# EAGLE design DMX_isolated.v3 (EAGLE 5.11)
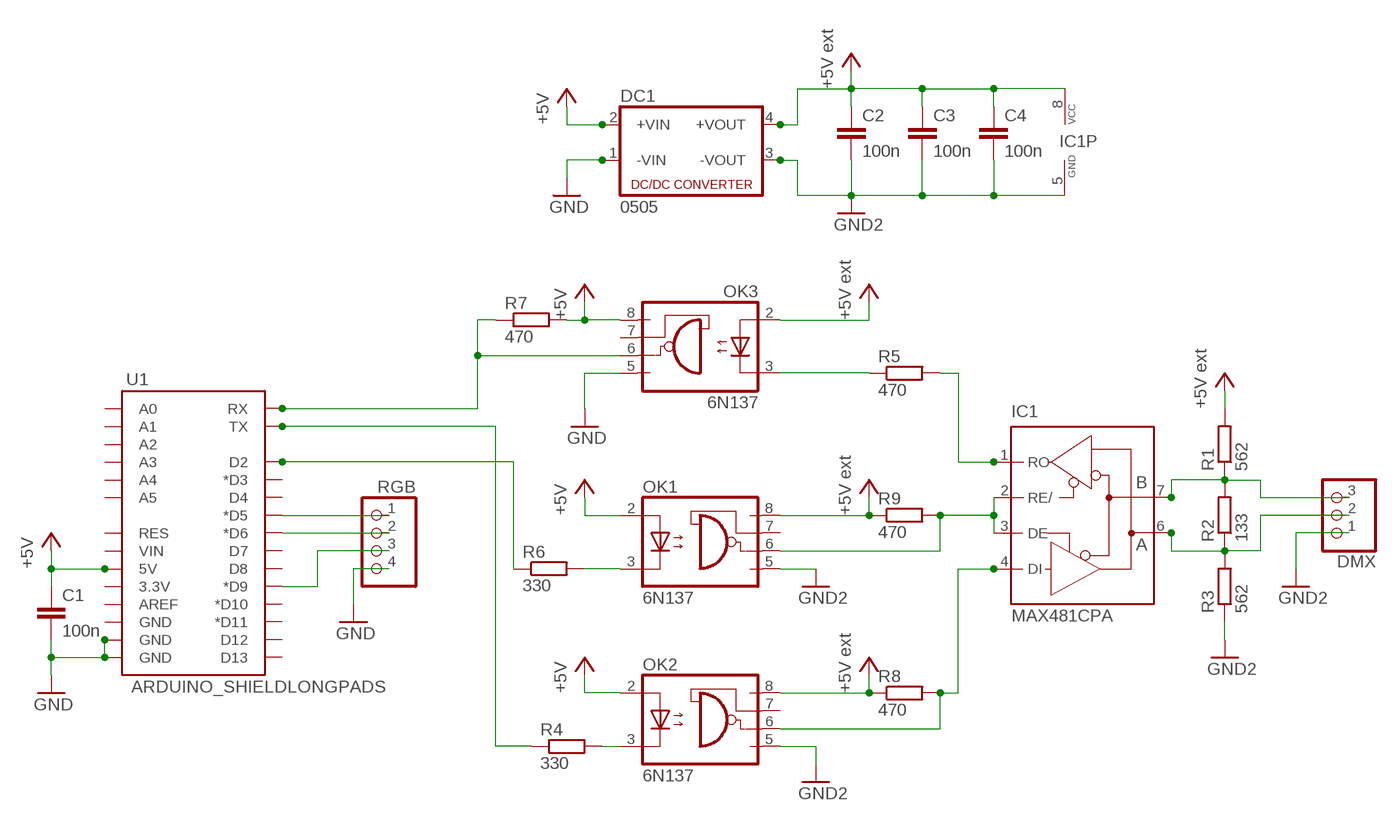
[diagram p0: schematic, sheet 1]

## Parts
C1  100n  C5/3  [C5B3]
C2  100n  C7.5/3  [C7.5B3]
C3  100n  C7.5/3  [C7.5B3]
C4  100n  C7.5/3  [C7.5B3]
DC1  0505  NME  [NME]
DMX  PINHD-1X3  [1X03]
IC1  MAX481CPA  [DIL08]
OK1  6N137  [DIL08]
OK2  6N137  [DIL08]
OK3  6N137  [DIL08]
R1  562  R-EU_0207/10  [0207/10]
R2  133  R-EU_0207/10  [0207/10]
R3  562  R-EU_0207/10  [0207/10]
R4  330  R-EU_0207/10  [0207/10]
R5  470  R-EU_0207/10  [0207/10]
R6  330  R-EU_0207/10  [0207/10]
R7  470  R-EU_0207/10  [0207/10]
R8  470  R-EU_0207/10  [0207/10]
R9  470  R-EU_0207/10  [0207/10]
RGB  PINHD-1X4  [1X04]
U1  ARDUINO_SHIELDLONGPADS  [DUEMILANOVE_SHIELD_LONGPADS]

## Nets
+5V: C1.1 DC1.2(+VIN) OK1.2(A) OK2.2(A) OK3.8(VCC) R7.2 U1.5V
+5V_EXT: C2.1 C3.1 C4.1 DC1.4(+VOUT) IC1.8(VCC) OK1.8(VCC) OK2.8(VCC) OK3.2(A) R1.2 R8.1 R9.1 ; supply symbol labelled +5V ext
D2: R4.1 U1.TX
GND: C1.2 DC1.1(-VIN) OK3.5(GND) RGB.4 U1.GND@0(GND) U1.GND@1(GND)
GND_EXT: C2.2 C3.2 C4.2 DC1.3(-VOUT) DMX.1 IC1.5(GND) OK1.5(GND) OK2.5(GND) R3.1 ; supply symbol labelled GND2
N$1: R6.1 U1.D2
N$2: RGB.1 U1.D5(*D5)
N$3: OK1.3(C) R6.2
N$4: RGB.2 U1.D6(*D6)
N$5: OK2.3(C) R4.2
N$6: IC1.2(RE/) IC1.3(DE) OK1.6(VO) R9.2
N$7: IC1.4(DI) OK2.6(VO) R8.2
N$8: OK3.3(C) R5.1
N$9: IC1.1(RO) R5.2
N$10: OK3.6(VO) R7.1 U1.RX
N$11: RGB.3 U1.D9(*D9)
N$15: DMX.3 IC1.7(B) R1.1 R2.2
N$17: DMX.2 IC1.6(A) R2.1 R3.2
Unconnected: OK1.7(VE) OK2.7(VE) OK3.7(VE) U1.3.3V U1.A0 U1.A1 U1.A2 U1.A3 U1.A4 U1.A5 U1.AREF U1.D3(*D3) U1.D4 U1.D7 U1.D8 U1.D10(*D10) U1.D11(*D11) U1.D12 U1.D13 U1.GND@2(GND) U1.RES U1.VIN

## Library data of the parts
C1-C4 = capacitor-wima:C: CAPACITOR
DC1 = dc-dc-converter:NME: DC-DC CONVERTER; MF: C & D TECHNOLOGIES, INC; MPN: NME1205D; OC_FARNELL: 1021466; OC_NEWARK: 98B8198
DMX = pinhead:PINHD-1X3: PIN HEADER
IC1 = maxim:MAX481CPA: RS485 TRANSEIVER; MPN: MAX481CPA+; OC_FARNELL: unknown; OC_NEWARK: 99K3445
OK1-OK3 = optocoupler:6N137: MOTOROLA OPTO COUPLER; MPN: 6N137; OC_FARNELL: 1328376; OC_NEWARK: 52M1895
R1-R9 = resistor:R-EU_: RESISTOR, European symbol
RGB = pinhead:PINHD-1X4: PIN HEADER
U1 = SparkFun:ARDUINO_SHIELD

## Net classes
1 power: width 0.508 mm

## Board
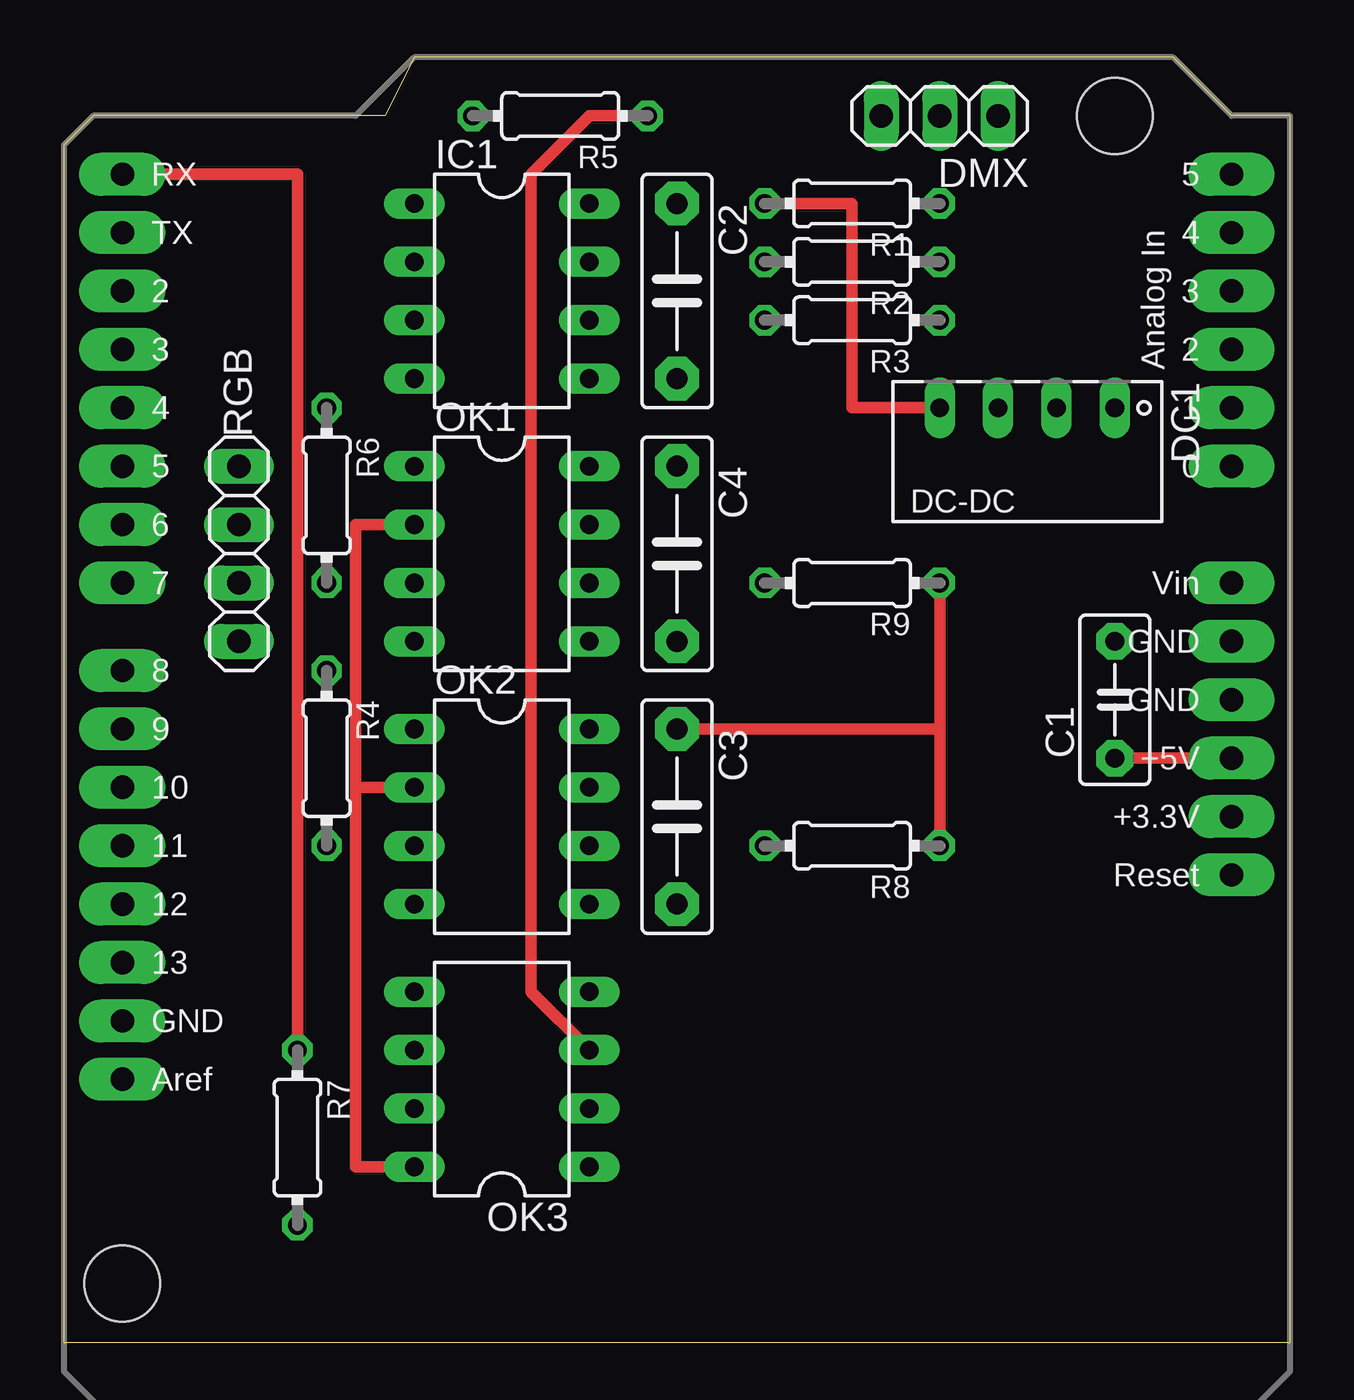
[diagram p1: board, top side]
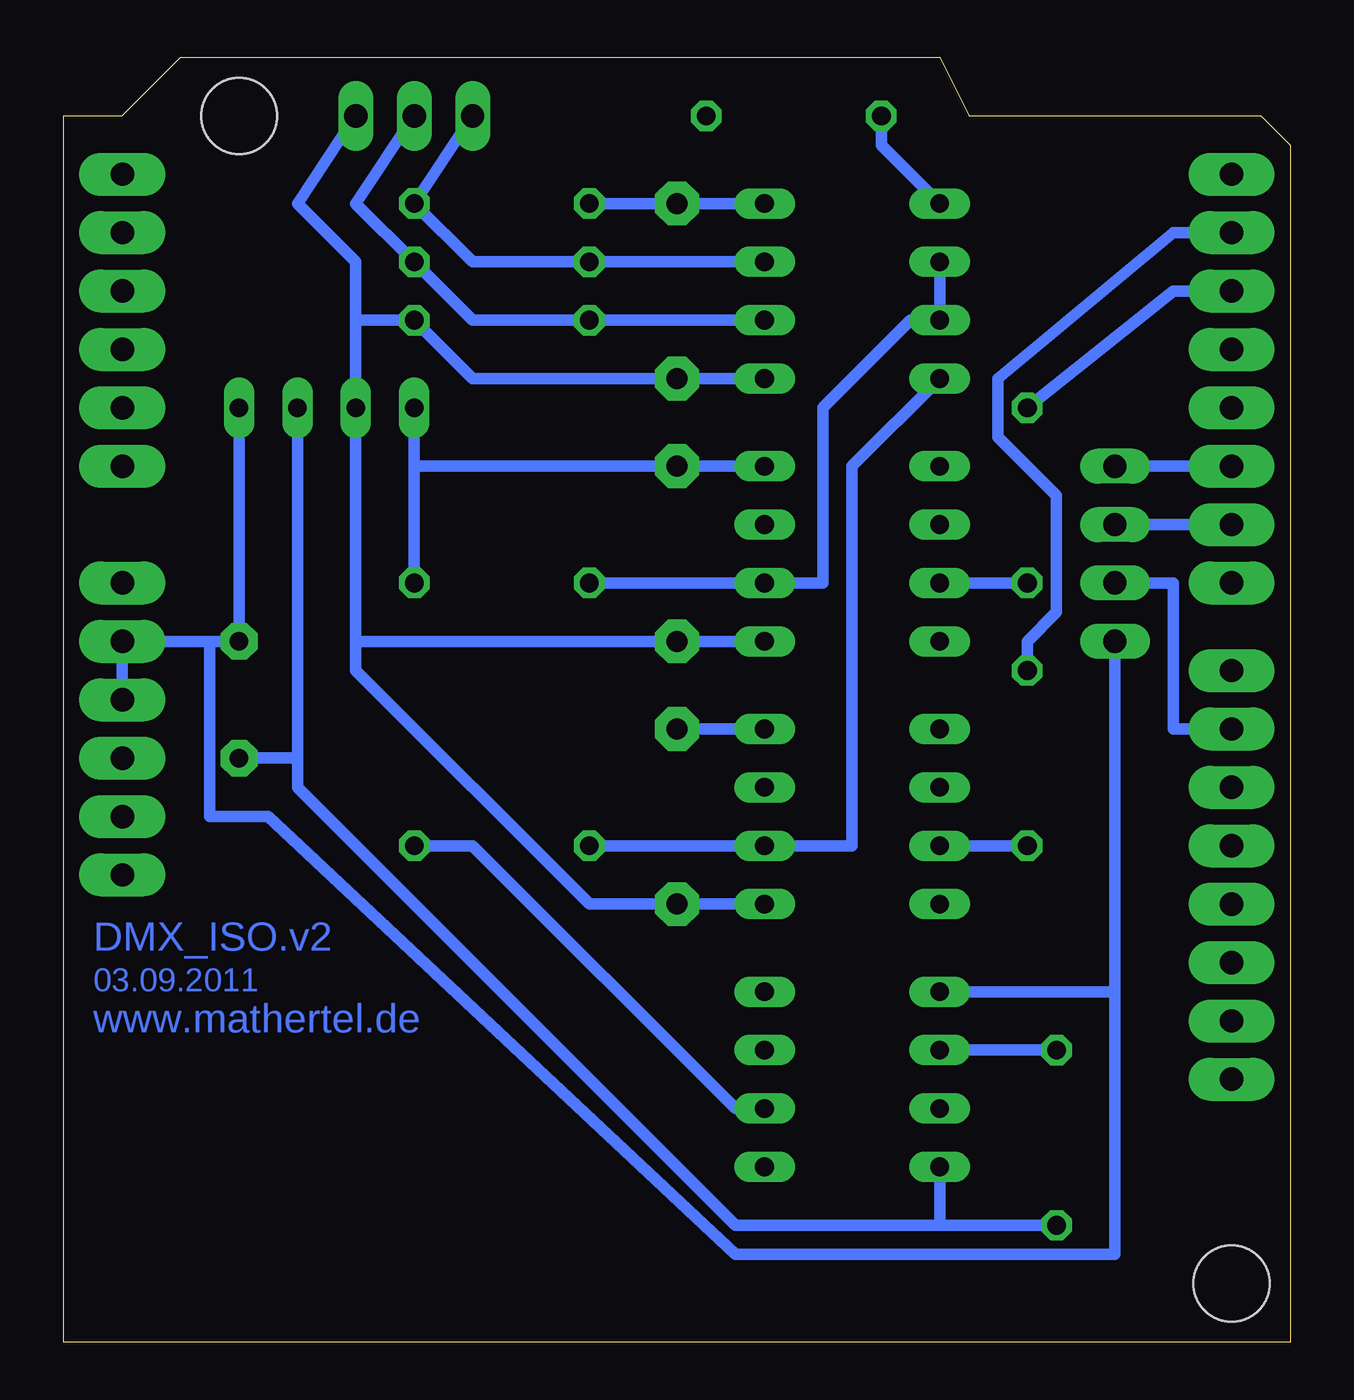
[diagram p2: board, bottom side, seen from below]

Size 53.34 x 55.88 mm. Coordinates in mm from the lower left corner, seen from the top.
Outline: 53.34,0 53.34,53.34 50.8,53.34 48.26,55.88 15.24,55.88 13.97,53.34 1.27,53.34 0,52.07 0,0 53.34,0
Copper layers (1*16): Top 0.035mm / dielectric 1.5mm / Bottom 0.035mm
Design rules "default *": minimum track width 20mil, minimum drill 24mil, track to track 8mil, track to pad 8mil, pad to pad 8mil, via to via 8mil, smd to smd 8mil, copper to edge 25mil, drill to drill 8mil, minimum pad ring 10mil, minimum via ring 8mil, stop-mask expansion 4mil, vias tented up to drill 0mil, thermal gap 10mil

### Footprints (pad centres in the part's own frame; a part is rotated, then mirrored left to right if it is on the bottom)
C5B3 = drill 0.813 pad 1.6 octagon: 1 -2.54,0; 2 2.54,0
C7.5B3 = drill 0.914 pad 1.905 octagon: 1 -3.81,0; 2 3.81,0
NME = drill 0.813 long: 1 0,3.81; 2 0,1.27; 3 0,-1.27; 4 0,-3.81
1X03 = drill 1.016 long: 1 -2.54,0; 2 0,0; 3 2.54,0
DIL08 = drill 0.813 long: 1 -3.81,-3.81; 2 -1.27,-3.81; 3 1.27,-3.81; 4 3.81,-3.81; 5 3.81,3.81; 6 1.27,3.81; 7 -1.27,3.81; 8 -3.81,3.81
0204/7 = drill 0.813 octagon: 1 -3.81,0; 2 3.81,0
1X04 = drill 1.016 long: 1 -3.81,0; 2 -1.27,0; 3 1.27,0; 4 3.81,0
DUEMILANOVE_SHIELD_LONGPADS = drill 1.016 pad 1.88 long: 3.3V 50.8,26.67; 5V 50.8,29.21; A0 50.8,41.91; A1 50.8,44.45; A2 50.8,46.99; A3 50.8,49.53; A4 50.8,52.07; A5 50.8,54.61; AREF 2.54,15.24; D2 2.54,49.53; D3 2.54,46.99; D4 2.54,44.45; D5 2.54,41.91; D6 2.54,39.37; D7 2.54,36.83; D8 2.54,33.02; D9 2.54,30.48; D10 2.54,27.94; D11 2.54,25.4; D12 2.54,22.86; D13 2.54,20.32; GND@0 50.8,31.75; GND@1 50.8,34.29; GND@2 2.54,17.78; RES 50.8,24.13; RX 2.54,54.61; TX 2.54,52.07; VIN 50.8,36.83 | hole 3.302: 45.72,57.15; 2.54,6.35

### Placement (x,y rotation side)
C1  45.72,27.94 90 top
C2  26.67,45.72 270 top
C3  26.67,22.86 270 top
C4  26.67,34.29 270 top
DC1  41.91,40.64 270 top
DMX  38.1,53.34 180 top
IC1  19.05,45.72 270 top
OK1  19.05,34.29 270 top
OK2  19.05,22.86 270 top
OK3  19.05,11.43 90 top
R1  562  [0204/7]  34.29,49.53 180 top
R2  133  [0204/7]  34.29,46.99 180 top
R3  562  [0204/7]  34.29,44.45 180 top
R4  330  [0204/7]  11.43,25.4 270 top
R5  470  [0204/7]  21.59,53.34 180 top
R6  330  [0204/7]  11.43,36.83 270 top
R7  470  [0204/7]  10.16,8.89 270 top
R8  470  [0204/7]  34.29,21.59 180 top
R9  470  [0204/7]  34.29,33.02 180 top
RGB  7.62,34.29 270 top
U1  0,-3.81 0 top

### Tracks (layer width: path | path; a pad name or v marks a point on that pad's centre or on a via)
+5V
  Top 0.508: C1.1 U1.5V | OK3.8 12.7,7.62 12.7,24.13 | 12.7,24.13 OK2.2 | 12.7,24.13 12.7,35.56 OK1.2
  Bottom 0.508: R7.2 15.24,5.08 | 15.24,5.08 OK3.8 | 43.18,25.4 C1.1 | 43.18,25.4 43.18,24.13 24.13,5.08 15.24,5.08 | 43.18,25.4 DC1.2
+5V_EXT
  Top 0.508: DC1.4 34.29,40.64 34.29,49.53 R1.2 | 38.1,26.67 R9.1 | R8.1 38.1,26.67 | 38.1,26.67 C3.1
  Bottom 0.508: IC1.8 C2.1 R1.2 | C3.1 OK2.8 | OK1.8 C4.1 38.1,38.1 | R9.1 38.1,38.1 | 38.1,38.1 DC1.4 | R8.1 35.56,21.59 24.13,10.16 OK3.2
D2
  Bottom 0.508: R4.1 11.43,30.48 10.16,31.75 10.16,36.83 12.7,39.37 12.7,41.91 5.08,48.26 U1.TX
GND
  Bottom 0.508: U1.GND@0 U1.GND@1 46.99,30.48 | DC1.1 C1.2 46.99,30.48 | 46.99,30.48 46.99,22.86 44.45,22.86 24.13,3.81 7.62,3.81 7.62,15.24 | 7.62,15.24 RGB.4 | OK3.5 7.62,15.24
GND_EXT
  Bottom 0.508: DMX.1 43.18,49.53 40.64,46.99 40.64,44.45 | 40.64,44.45 R3.1 35.56,41.91 C2.2 IC1.5 | 40.64,44.45 DC1.3 40.64,30.48 | 40.64,30.48 C4.2 OK1.5 | 40.64,30.48 40.64,29.21 30.48,19.05 C3.2 OK2.5
N$1
  Bottom 0.508: R6.1 5.08,45.72 U1.D2
N$2
  Bottom 0.508: U1.D5 RGB.1
N$3
  Bottom 0.508: R6.2 OK1.3
N$4
  Bottom 0.508: U1.D6 RGB.2
N$5
  Bottom 0.508: 13.97,21.59 OK2.3 R4.2
N$6
  Bottom 0.508: IC1.2 IC1.3 16.51,44.45 20.32,40.64 20.32,33.02 OK1.6 R9.2
N$7
  Bottom 0.508: IC1.4 19.05,38.1 19.05,21.59 OK2.6 R8.2
N$8
  Top 0.508: R5.1 22.86,53.34 20.32,50.8 20.32,15.24 OK3.3
N$9
  Bottom 0.508: IC1.1 17.78,52.07 R5.2
N$10
  Top 0.508: U1.RX 10.16,50.8 R7.1
  Bottom 0.508: R7.1 OK3.6
N$11
  Bottom 0.508: RGB.3 5.08,33.02 5.08,26.67 U1.D9
N$15
  Bottom 0.508: DMX.3 R1.1 35.56,46.99 R2.2 IC1.7
N$17
  Bottom 0.508: DMX.2 40.64,49.53 R2.1 35.56,44.45 R3.2 IC1.6

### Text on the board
Bottom: DMX_ISO.v2 | 03.09.2011 | www.mathertel.de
